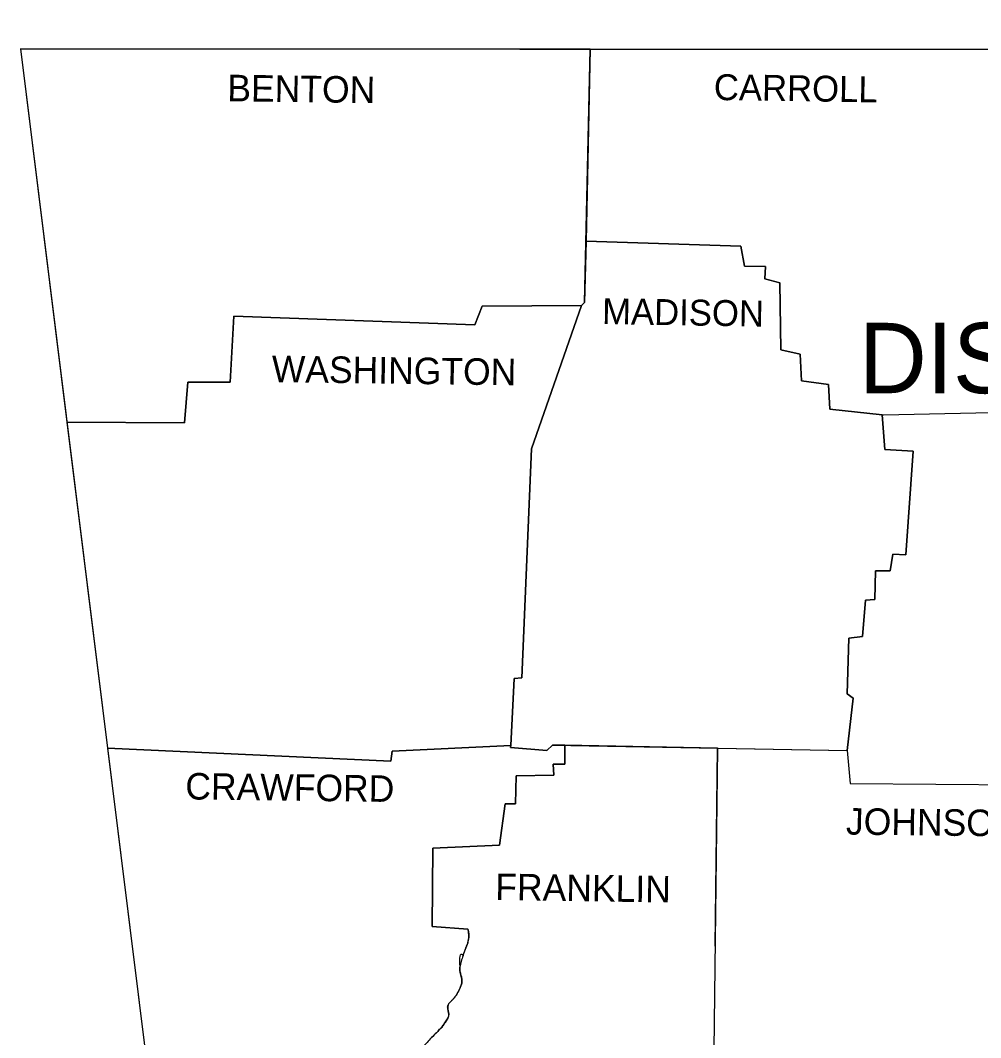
# Model space of a CAD drawing. Extents: x -13171 to 18763, y -8840 to 11152.
# Drawn here: x 10745 to 12267, y 8746 to 10358 of the extents above; entities that cross this region are included whole.
import ezdxf

# ---------------------------------------------------------------- set-up
doc = ezdxf.new("R2010")
doc.units = 0
for name, color, linetype in [('Level 1', 7, 'Continuous'), ('Level 2', 7, 'Continuous'), ('Level 3', 7, 'Continuous'), ('Level 48', 7, 'Continuous'), ('Level 50', 7, 'Continuous')]:
    doc.layers.add(name, color=color, linetype=linetype)

msp = doc.modelspace()

# ---------------------------------------------------------------- linework, layer by layer
at = {"layer": 'Level 1'}
for points in [[(10745.390580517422, 10312.988270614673), (12327.474404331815, 10312.009863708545), (13715.833678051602, 10314.94508427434), (15353.686690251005, 10340.383661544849), (16112.930380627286, 10357.994984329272)], [(10745.390580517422, 10312.988270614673), (10947.920791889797, 8686.876140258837), (10859.864178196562, 6032.458444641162)], [(11648.578114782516, 10312.42971302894), (11639.654411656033, 9910.8630686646)], [(11641.810298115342, 10007.87796022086), (11887.191336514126, 9999.898089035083), (11893.061777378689, 9968.589070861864), (11926.327609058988, 9967.610664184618), (11925.349202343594, 9948.042527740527), (11948.830965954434, 9942.172086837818), (11950.787779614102, 9835.52574368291), (11981.118390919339, 9828.676896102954), (11983.07520454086, 9786.60540295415), (12026.125104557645, 9780.73496205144), (12028.081918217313, 9741.598689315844), (12113.203311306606, 9732.793027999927), (12332.366438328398, 9737.685061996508), (12334.364140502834, 10312.024429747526)], [(10819.11309812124, 9721.071245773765), (11005.646794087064, 9720.073739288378), (11010.538828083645, 9784.648589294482), (11078.048898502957, 9784.648589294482), (11083.919339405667, 9889.338118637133), (11465.497998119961, 9875.640423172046), (11477.238879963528, 9904.992627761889), (11634.762377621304, 9905.971034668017), (11555.51142543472, 9678.980652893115), (11539.856916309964, 9315.991723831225), (11528.116034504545, 9315.013316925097), (11522.245593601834, 9205.431753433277), (11579.9715957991, 9200.539719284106), (11588.777257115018, 9209.345380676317), (12055.477309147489, 9200.539719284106), (12060.369343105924, 9148.684157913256)], [(12111.08531866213, 9733.012130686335), (12115.160124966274, 9678.002246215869), (12160.166838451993, 9675.067025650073), (12148.425956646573, 9510.694680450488), (12127.879413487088, 9511.673087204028), (12123.965786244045, 9485.25610317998), (12100.48402259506, 9485.25610317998), (12099.50561584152, 9440.249389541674), (12084.829513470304, 9439.270982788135), (12079.93747951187, 9381.544980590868), (12058.412529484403, 9378.609760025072), (12055.477309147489, 9290.553146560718), (12065.261377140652, 9283.70429875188), (12055.477309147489, 9200.539719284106)], [(12060.369343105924, 9148.684157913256), (13146.400910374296, 9139.878496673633), (13151.292944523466, 9242.611212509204), (13406.280234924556, 9239.64624397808)], [(10883.435220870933, 9204.629854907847), (11332.434670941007, 9183.906803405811), (11334.391484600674, 9199.561312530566), (11522.408215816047, 9208.467368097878)], [(11608.34539344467, 9208.97893617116), (11608.345393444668, 9179.014769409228), (11589.755664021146, 9179.014769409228), (11590.734070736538, 9161.403446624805), (11531.051254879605, 9160.42503979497), (11530.072848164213, 9116.396732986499), (11513.439932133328, 9116.396732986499), (11504.634270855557, 9050.84347630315), (11398.966334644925, 9045.951442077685), (11397.987927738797, 8921.693776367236), (11454.735523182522, 8917.780149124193)], [(11850.011877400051, 9204.453346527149), (11843.163029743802, 8639.912612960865)]]:
    msp.add_lwpolyline(points, dxfattribs=at)
msp.add_spline([(11454.735523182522, 8917.780149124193), (11455.612357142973, 8912.663859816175), (11455.98488757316, 8907.452184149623), (11454.735523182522, 8897.233606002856), (11452.950627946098, 8891.815859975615), (11450.895159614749, 8886.475128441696), (11448.803059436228, 8881.13239818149), (11446.908268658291, 8875.70865597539), (11442.016234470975, 8857.118926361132), (11442.023444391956, 8851.055816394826), (11443.52192513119, 8844.908468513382), (11445.001365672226, 8838.75130696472), (11445.261973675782, 8835.692303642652), (11444.951454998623, 8832.658755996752), (11441.344939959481, 8822.595474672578), (11436.145793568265, 8813.090619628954), (11433.14169039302, 8808.983337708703), (11429.65109198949, 8805.249909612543), (11426.228022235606, 8801.523209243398), (11423.426505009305, 8797.436110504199), (11422.612506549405, 8792.784643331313), (11423.493055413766, 8787.660128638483), (11424.340329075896, 8782.531570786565), (11423.426505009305, 8777.867974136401), (11421.86730924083, 8775.122246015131), (11420.243552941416, 8772.4075669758), (11416.774155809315, 8767.110635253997), (11412.961907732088, 8762.055737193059), (11408.750402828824, 8757.321431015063), (11393.095893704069, 8741.666921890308), (11386.858936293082, 8734.618487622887), (11383.480516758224, 8731.392237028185), (11381.552216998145, 8730.044901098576), (11380.506531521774, 8729.461592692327), (11379.398198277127, 8728.94763340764), (11373.352562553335, 8727.29911046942), (11367.233335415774, 8726.893252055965), (11361.081497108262, 8727.02538090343), (11358.006155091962, 8727.072978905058), (11354.938027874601, 8726.990819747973), (11344.665047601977, 8726.513200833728), (11334.391484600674, 8726.012412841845), (11329.067462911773, 8725.490061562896), (11323.889080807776, 8724.384519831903), (11318.82526482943, 8722.38071269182), (11316.326608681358, 8720.943498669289), (11313.844941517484, 8719.163565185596), (11310.609534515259, 8715.935386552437), (11308.365609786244, 8712.349359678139), (11306.904537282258, 8708.501409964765), (11306.017686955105, 8704.487462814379), (11306.256050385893, 8698.874063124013), (11307.898550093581, 8693.225334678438), (11309.579025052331, 8687.581831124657), (11309.931314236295, 8681.984106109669), (11309.018511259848, 8676.43069044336), (11307.614201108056, 8670.957855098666), (11302.104059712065, 8660.459156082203), (11292.458280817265, 8650.956737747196), (11281.557516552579, 8643.826240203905), (11270.524128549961, 8637.809323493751), (11259.054159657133, 8633.063765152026), (11253.2193963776, 8631.832798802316), (11247.203108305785, 8631.353586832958), (11241.241904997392, 8630.7510571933), (11235.572396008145, 8629.15013783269), (11227.440015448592, 8625.385856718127), (11219.402375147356, 8621.412684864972), (11211.377889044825, 8617.394612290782), (11203.284971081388, 8613.49562901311), (11173.932766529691, 8600.776340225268), (11166.283379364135, 8598.962229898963), (11158.23528129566, 8598.846966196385), (11150.208671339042, 8600.185592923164), (11142.62374850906, 8602.733153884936), (11113.271543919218, 8615.452442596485), (11086.854559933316, 8627.193324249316), (11081.360377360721, 8629.498790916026), (11075.895197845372, 8631.906088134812), (11070.77306355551, 8634.892223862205), (11068.438776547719, 8636.751421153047), (11067.345502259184, 8637.798638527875), (11066.30801665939, 8638.934206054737), (11060.75323199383, 8647.416196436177), (11056.896773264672, 8656.60846252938), (11053.587707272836, 8666.013863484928), (11051.778779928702, 8670.641133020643), (11049.675100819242, 8675.135258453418), (11044.466597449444, 8684.975578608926), (11038.912625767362, 8694.703394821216), (11035.152842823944, 8700.255734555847), (11030.870011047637, 8705.305141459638), (11025.961054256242, 8709.945709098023), (11023.239567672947, 8712.142082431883), (11020.322896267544, 8714.271531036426), (11014.883142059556, 8717.379374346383), (11009.27083741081, 8719.504022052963), (11003.558723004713, 8720.969237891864), (10997.819539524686, 8722.098785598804), (10993.203239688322, 8722.872284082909), (10988.454518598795, 8723.159201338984), (10983.74087555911, 8722.426707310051), (10981.449551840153, 8721.511671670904), (10979.22980987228, 8720.141971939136), (10967.173548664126, 8709.249197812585), (10958.160238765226, 8697.140161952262), (10951.715223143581, 8684.01835777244), (10949.307495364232, 8677.141259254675), (10947.363844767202, 8670.087278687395)], degree=3, dxfattribs=at)
at = {"layer": 'Level 48'}
for p, q in [((11648.578114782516, 10312.429713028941), (10745.390580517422, 10312.988270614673)), ((10745.390580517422, 10312.988270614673), (10819.11309812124, 9721.071245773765)), ((11639.654411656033, 9910.8630686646), (11648.578114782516, 10312.42971302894)), ((11648.578114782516, 10312.42971302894), (11641.810298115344, 10007.87796022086)), ((11641.810298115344, 10007.87796022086), (11639.654411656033, 9910.8630686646)), ((11925.349202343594, 9948.042527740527), (11926.327609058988, 9967.610664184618)), ((11634.762377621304, 9905.971034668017), (11555.51142543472, 9678.980652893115)), ((11634.762377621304, 9905.971034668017), (11639.654411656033, 9910.8630686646)), ((11639.654411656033, 9910.8630686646), (11634.762377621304, 9905.971034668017)), ((11010.538828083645, 9784.648589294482), (11005.646794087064, 9720.073739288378)), ((12111.08531866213, 9733.012130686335), (12028.081918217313, 9741.598689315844)), ((11005.646794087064, 9720.073739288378), (10819.11309812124, 9721.071245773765)), ((10819.11309812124, 9721.071245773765), (10883.435220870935, 9204.629854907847)), ((11555.51142543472, 9678.980652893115), (11539.856916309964, 9315.991723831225)), ((11522.408215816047, 9208.467368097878), (11528.116034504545, 9315.013316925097)), ((11334.391484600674, 9199.561312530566), (11522.408215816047, 9208.467368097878)), ((11522.408215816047, 9208.467368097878), (11334.391484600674, 9199.561312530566)), ((11522.408215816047, 9208.467368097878), (11522.245593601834, 9205.431753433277)), ((11522.245593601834, 9205.431753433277), (11522.408215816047, 9208.467368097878)), ((11608.345393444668, 9179.014769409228), (11608.34539344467, 9208.976170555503)), ((10883.435220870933, 9204.629854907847), (11332.434670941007, 9183.906803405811)), ((11332.434670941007, 9183.906803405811), (10883.435220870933, 9204.629854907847)), ((11332.434670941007, 9183.906803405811), (11334.391484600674, 9199.561312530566)), ((11334.391484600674, 9199.561312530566), (11332.434670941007, 9183.906803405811)), ((11522.245593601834, 9205.431753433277), (11579.9715957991, 9200.539719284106)), ((11579.9715957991, 9200.539719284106), (11522.245593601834, 9205.431753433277)), ((11846.20650763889, 8890.782150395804), (11850.011429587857, 9204.416434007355)), ((11850.0111810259, 9204.416438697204), (12055.477309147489, 9200.539719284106)), ((11850.011877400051, 9204.453346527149), (11850.011429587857, 9204.416434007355)), ((11446.908268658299, 8875.708655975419), (11448.673417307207, 8880.79522819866)), ((11442.016234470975, 8857.118926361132), (11442.309396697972, 8858.5781148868)), ((11417.142367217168, 8767.648091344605), (11420.243552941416, 8772.4075669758)), ((11404.87267716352, 8753.36946063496), (11406.807536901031, 8755.313463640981)), ((11396.970801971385, 8745.614881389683), (11400.921270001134, 8749.491502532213))]:
    msp.add_line(p, q, dxfattribs=at)
for points in [[(12334.364140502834, 10312.024429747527), (12327.474404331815, 10312.009863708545), (11648.578114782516, 10312.429713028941)], [(11641.810298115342, 10007.87796022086), (11887.191336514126, 9999.898089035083), (11893.061777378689, 9968.589070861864), (11926.327609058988, 9967.610664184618), (11925.349202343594, 9948.042527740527), (11948.830965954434, 9942.172086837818), (11950.787779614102, 9835.52574368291), (11981.118390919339, 9828.676896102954), (11983.07520454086, 9786.60540295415), (12026.125104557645, 9780.73496205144), (12028.081918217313, 9741.598689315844), (12111.08531866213, 9733.012130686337), (12113.203311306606, 9732.793027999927), (12332.366438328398, 9737.685061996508)], [(11926.327609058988, 9967.610664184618), (11893.061777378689, 9968.589070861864), (11887.191336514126, 9999.898089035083), (11641.810298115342, 10007.87796022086)], [(11950.787779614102, 9835.52574368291), (11948.830965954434, 9942.172086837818), (11925.349202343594, 9948.042527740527)], [(10819.11309812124, 9721.071245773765), (11005.646794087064, 9720.073739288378), (11010.538828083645, 9784.648589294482), (11078.048898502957, 9784.648589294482), (11083.919339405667, 9889.338118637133), (11465.497998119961, 9875.640423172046), (11477.238879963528, 9904.992627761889), (11634.762377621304, 9905.971034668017)], [(11634.762377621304, 9905.971034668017), (11477.238879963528, 9904.992627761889), (11465.497998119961, 9875.640423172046), (11083.919339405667, 9889.338118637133), (11078.048898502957, 9784.648589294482), (11010.538828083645, 9784.648589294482)], [(11528.116034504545, 9315.013316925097), (11539.856916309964, 9315.991723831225), (11555.51142543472, 9678.980652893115), (11634.762377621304, 9905.971034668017)], [(11983.07520454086, 9786.60540295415), (11981.118390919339, 9828.676896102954), (11950.787779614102, 9835.52574368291)], [(12028.081918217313, 9741.598689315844), (12026.125104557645, 9780.73496205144), (11983.07520454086, 9786.60540295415)], [(12055.477309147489, 9200.539719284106), (12065.261377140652, 9283.70429875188), (12055.477309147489, 9290.553146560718), (12058.412529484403, 9378.609760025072), (12079.93747951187, 9381.544980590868), (12084.829513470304, 9439.270982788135), (12099.50561584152, 9440.249389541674), (12100.48402259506, 9485.25610317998), (12123.965786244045, 9485.25610317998), (12127.879413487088, 9511.673087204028), (12148.425956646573, 9510.694680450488), (12160.166838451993, 9675.067025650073), (12115.160124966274, 9678.002246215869), (12111.08531866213, 9733.012130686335)], [(11539.856916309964, 9315.991723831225), (11528.116034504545, 9315.013316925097), (11522.408215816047, 9208.467368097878)], [(11579.9715957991, 9200.539719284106), (11588.777257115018, 9209.345380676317), (11850.011877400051, 9204.453346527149)], [(11608.345341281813, 9208.976171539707), (11588.777257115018, 9209.345380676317), (11579.9715957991, 9200.539719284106)], [(11850.0111810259, 9204.416438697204), (11608.345393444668, 9208.976170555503)], [(10883.435220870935, 9204.629854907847), (10947.920791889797, 8686.876140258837), (10947.3638447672, 8670.087278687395)], [(11398.966334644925, 9045.951442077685), (11504.634270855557, 9050.84347630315), (11513.439932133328, 9116.396732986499), (11530.072848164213, 9116.396732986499), (11531.051254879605, 9160.42503979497), (11590.734070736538, 9161.403446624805), (11589.755664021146, 9179.014769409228), (11608.345393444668, 9179.014769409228)], [(11454.735523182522, 8917.780149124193), (11397.987927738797, 8921.693776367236), (11398.966334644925, 9045.951442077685)]]:
    msp.add_lwpolyline(points, dxfattribs=at)
for points, degree in [([(11455.985821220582, 8907.061444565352), (11455.986021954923, 8907.19169940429), (11455.98570565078, 8907.321947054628), (11455.98488757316, 8907.452184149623), (11455.973986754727, 8909.187582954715), (11455.822793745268, 8910.92841735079), (11455.612357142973, 8912.663859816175), (11455.403293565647, 8914.38797912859), (11455.123616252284, 8916.082325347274), (11454.735523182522, 8917.780149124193)], 3), ([(11454.260286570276, 8895.616888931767), (11454.424192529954, 8896.149243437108), (11454.582229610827, 8896.68732427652), (11454.735523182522, 8897.233606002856), (11455.64593767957, 8900.477987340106), (11455.98075190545, 8903.772008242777), (11455.985821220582, 8907.061444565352)], 3), ([(11448.803059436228, 8881.13239818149), (11449.49594192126, 8882.915379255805), (11450.202258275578, 8884.692448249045), (11450.895159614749, 8886.475128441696), (11451.586234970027, 8888.25311078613), (11452.267908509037, 8890.034136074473), (11452.950627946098, 8891.815859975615), (11453.432228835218, 8893.072715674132), (11453.863458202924, 8894.328019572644), (11454.260286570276, 8895.616888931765)], 3), ([(11443.52192513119, 8844.908468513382), (11443.026563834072, 8846.95846823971), (11442.516802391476, 8849.00532325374), (11442.023444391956, 8851.055816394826), (11441.5506892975, 8853.02067979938), (11441.6270487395, 8855.134665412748), (11442.016234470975, 8857.118926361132)], 3), ([(11441.344939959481, 8822.595474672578), (11442.892843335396, 8825.851255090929), (11444.112614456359, 8829.11854653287), (11444.951454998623, 8832.658755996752), (11445.190739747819, 8833.668623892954), (11445.274796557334, 8834.680007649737), (11445.261973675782, 8835.692303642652), (11445.249063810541, 8836.71146651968), (11445.237891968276, 8837.748202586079), (11445.001365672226, 8838.75130696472), (11444.513502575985, 8840.820326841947), (11444.017682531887, 8842.856829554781), (11443.52192513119, 8844.908468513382)], 3), ([(11435.530279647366, 8812.1458215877), (11435.73700903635, 8812.459096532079), (11435.941382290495, 8812.774617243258), (11436.145793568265, 8813.090619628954), (11438.120638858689, 8816.143561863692), (11439.776203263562, 8819.295874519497), (11441.344939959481, 8822.595474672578)], 3), ([(11426.890833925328, 8802.249189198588), (11427.808207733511, 8803.252938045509), (11428.726763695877, 8804.253198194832), (11429.65109198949, 8805.249909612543), (11429.93788957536, 8805.55916599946), (11430.225838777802, 8805.867207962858), (11430.514312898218, 8806.174720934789)], 3), ([(11430.514312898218, 8806.174720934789), (11431.39112186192, 8807.109397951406), (11432.272780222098, 8808.039187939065), (11433.14169039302, 8808.983337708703), (11434.038051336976, 8809.957315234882), (11434.798910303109, 8811.037514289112), (11435.530279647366, 8812.145821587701)], 3), ([(11422.612506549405, 8792.784643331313), (11422.354497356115, 8794.335953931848), (11422.68832376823, 8795.887112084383), (11423.426505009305, 8797.436110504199), (11424.201098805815, 8799.061516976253), (11425.113680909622, 8800.301506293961), (11426.228022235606, 8801.523209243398), (11426.44893364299, 8801.765404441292), (11426.669849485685, 8802.007398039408), (11426.890833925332, 8802.24918919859)], 3), ([(11423.493055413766, 8787.660128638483), (11423.204935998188, 8789.368467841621), (11422.896603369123, 8791.076477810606), (11422.612506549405, 8792.784643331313)], 2), ([(11424.381238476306, 8780.960153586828), (11424.432548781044, 8781.484809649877), (11424.422563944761, 8782.01039098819), (11424.340329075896, 8782.531570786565), (11424.070604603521, 8784.24100314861), (11423.781089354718, 8785.952296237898), (11423.493055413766, 8787.660128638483)], 3), ([(11420.243552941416, 8772.4075669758), (11420.651055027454, 8773.073024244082), (11421.049148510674, 8773.743159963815), (11421.446986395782, 8774.413965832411)], 2), ([(11421.44698639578, 8774.413965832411), (11421.58699269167, 8774.650034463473), (11421.726967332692, 8774.886186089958), (11421.86730924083, 8775.122246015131), (11422.405473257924, 8776.027456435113), (11422.923301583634, 8776.872423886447), (11423.426505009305, 8777.867974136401), (11423.931289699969, 8778.866652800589), (11424.278687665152, 8779.911555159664), (11424.381238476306, 8780.960153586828)], 3), ([(11412.961907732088, 8762.055737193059), (11414.306651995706, 8763.687954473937), (11415.577063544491, 8765.369102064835), (11416.774155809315, 8767.110635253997), (11416.897201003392, 8767.28964174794), (11417.019952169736, 8767.46878151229), (11417.142367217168, 8767.648091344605)], 3)]:
    msp.add_open_spline(points, degree=degree, dxfattribs=at)
for points in [[(11442.309396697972, 8858.578114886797), (11446.908268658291, 8875.70865597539), (11446.90826865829, 8875.708655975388)], [(11448.67341730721, 8880.79522819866), (11448.803059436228, 8881.13239818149), (11448.80305943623, 8881.13239818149)], [(11406.807536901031, 8755.313463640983), (11408.750402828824, 8757.321431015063), (11408.750402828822, 8757.321431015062)], [(11408.750402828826, 8757.321431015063), (11408.750402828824, 8757.321431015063), (11411.50648063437, 8760.340479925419)], [(11411.506480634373, 8760.340479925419), (11412.961907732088, 8762.055737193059), (11412.961907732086, 8762.055737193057)], [(11400.921270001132, 8749.491502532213), (11400.921270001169, 8749.491502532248), (11404.872677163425, 8753.369460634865), (11404.872677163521, 8753.36946063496)]]:
    msp.add_spline(points, degree=3, dxfattribs=at)
at = {"layer": 'Level 50'}
msp.add_line((11639.654411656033, 9910.8630686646), (11634.762377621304, 9905.971034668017), dxfattribs=at)

# ---------------------------------------------------------------- texts
at = {"layer": 'Level 2'}
for s, height, rotation, p in [('BENTON', 42.07344995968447, 359.2527055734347, (11073.156864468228, 10229.8236911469)), ('CARROLL', 41.09308632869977, 359.14808058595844, (11844.141436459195, 10231.780504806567)), ('MADISON', 41.093086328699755, 359.0906194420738, (11667.049802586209, 9876.618830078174)), ('WASHINGTON', 42.06170907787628, 359.232005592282, (11143.602155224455, 9784.648589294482)), ('CRAWFORD', 42.06170907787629, 359.27706391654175, (11006.625200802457, 9123.24558064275)), ('JOHNSON', 42.073449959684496, 359.35139723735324, (12053.52049548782, 9067.47639210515)), ('FRANKLIN', 42.07344995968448, 359.18154443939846, (11497.785423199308, 8963.76526951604))]:
    msp.add_text(s, height=height, rotation=rotation, dxfattribs=at).set_placement(p)
at = {"layer": 'Level 3'}
msp.add_text('DISTRICT 9', height=111.53837717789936, dxfattribs=at).set_placement((12074.067038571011, 9767.037266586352))

doc.saveas('drawing.dxf')
